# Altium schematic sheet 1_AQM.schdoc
size 309 x 223 mm; Symbol: Sheet-Symbol_A4; Device: Sheet-Symbol_A4; @Project Name: Air Quality Monitor; @Page Count: 1; @Update Date: 2024-08-29; @Create Date: 2024-08-23; @Schematic Name: Schematic1; @Page No: 1; @Page Name: AQM; Company: EasyEDA.com; Reviewed: EasyEDA; Version: V0.1; Page Size: A4; Part Number: JLCPCB-002; Drawn: EasyEDA; @Board Name: Board1; @Create Time: 15:16:23; @Update Time: 16:29:40
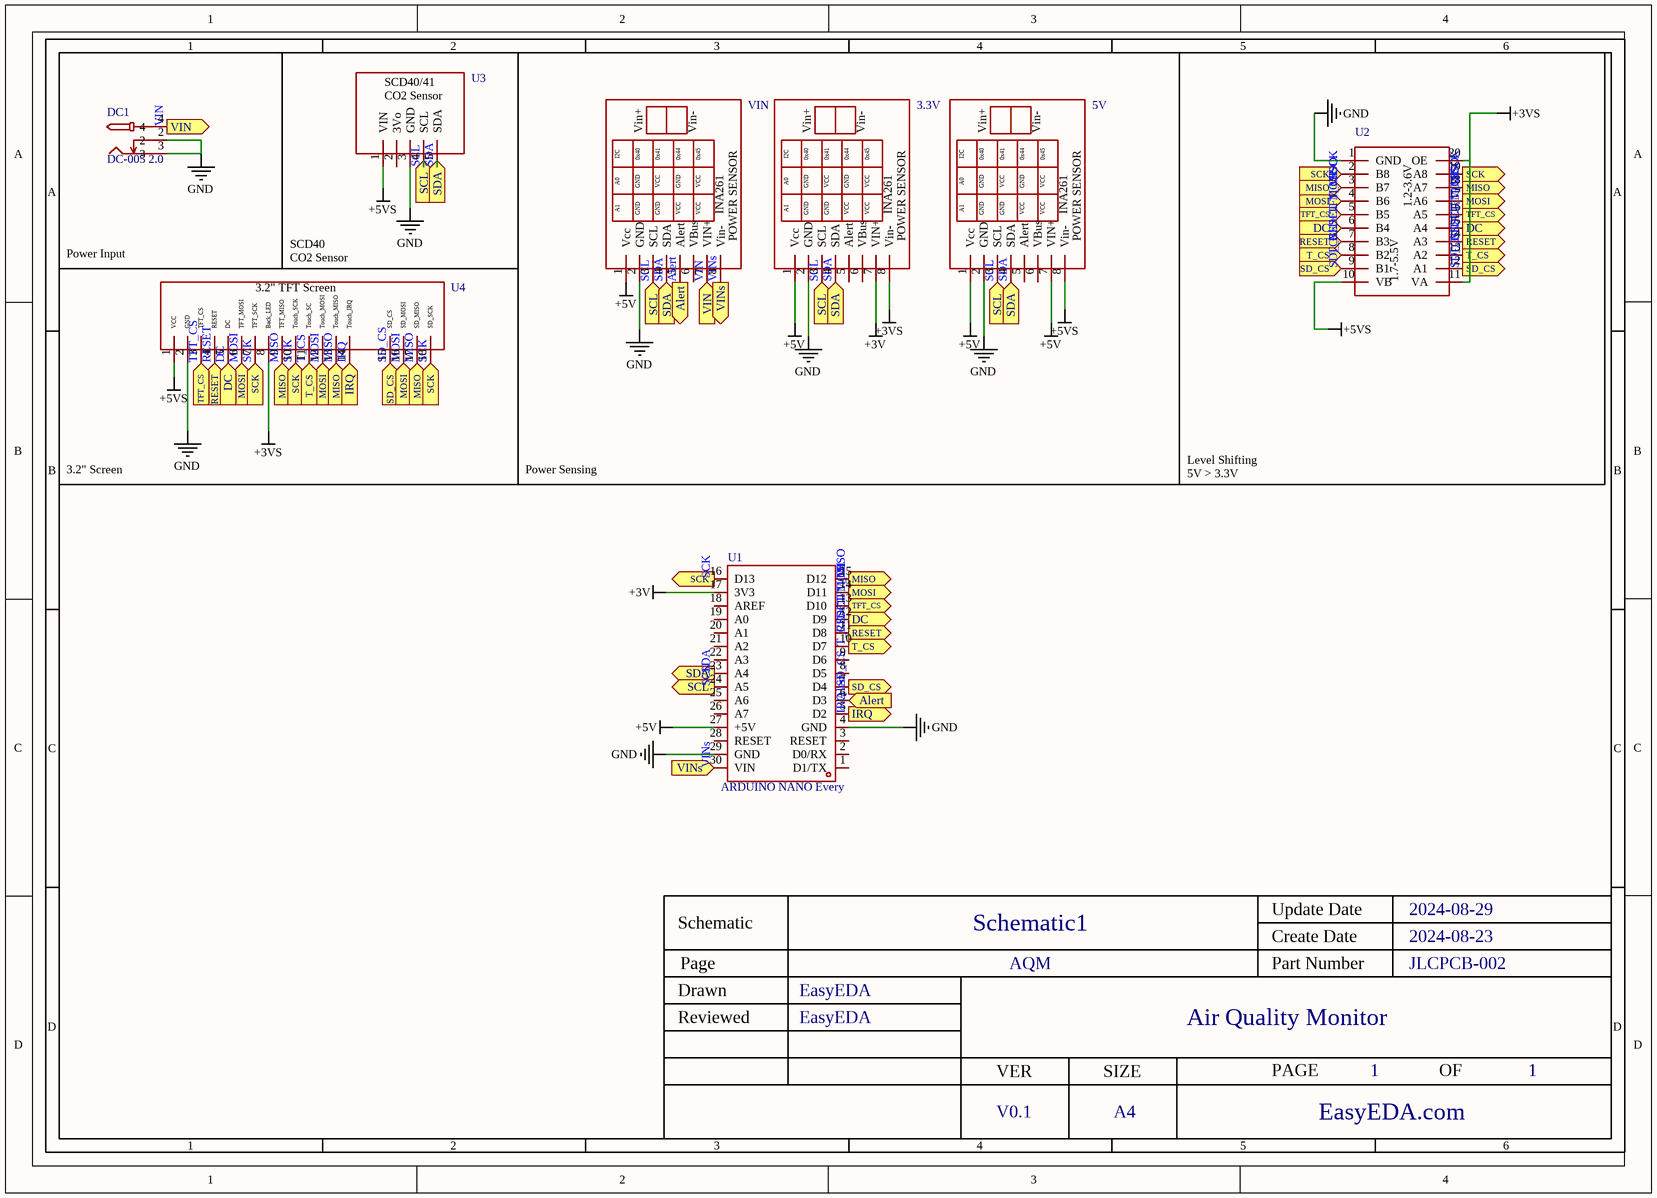
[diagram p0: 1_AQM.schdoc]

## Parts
3.3V  INA260 Breakout  [INA260 Breakout]  (value not drawn)
5V  INA260 Breakout  [INA260 Breakout]  (value not drawn)
DC1  DC-005 2.0  [DC-IN-TH_DC-5520-1]  (value not drawn)
U1  ARDUINO NANO Every  [COMM-TH_ARDUINO_NANO]  (value not drawn)
U2  8 Channel Level Shifter  [8 Channel Level Shifter Footprint]  (value not drawn)
U3  Adafruit SCD40/41 Breakout  [Adafruit SCD40/41]  (value not drawn)
U4  2.8" TFT Screen (SPI, Touch, SD)  [2.8" TFT Display Footprint 1]  (value not drawn)
VIN  INA260 Breakout  [INA260 Breakout]  (value not drawn)

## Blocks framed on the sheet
Power Input: DC1
Power Sensing: 3.3V 5V VIN
3.2" Screen: U4

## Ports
Alert (in), Alert (out), DC (in), DC (out), IRQ (in), IRQ (out), MISO (in), MISO (out), MOSI (in), MOSI (out), RESET (in), RESET (out), SCK (in), SCK (out), SCL (in), SCL (out), SD_CS (in), SD_CS (out), SDA (in), SDA (out), T_CS (in), T_CS (out), TFT_CS (in), TFT_CS (out), VIN (in), VIN (out), VINs (in), VINs (out)

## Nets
+3V: 3.3V.7(VIN+) U1.17(3V3)
+3VS: 3.3V.8(Vin-) U2.11(VA) U2.20(OE) U4.8(Back_LED)
+5V: 3.3V.1(Vcc) 5V.1(Vcc) 5V.7(VIN+) U1.27(+5V) VIN.1(Vcc)
+5VS: 5V.8(Vin-) U2.10(VB) U3.1(VIN) U4.1(VCC)
GND: 3.3V.2(GND) 5V.2(GND) DC1.2 DC1.3 U1.4(GND) U1.29(GND) U2.1(GND) U3.3(GND) U4.2(GND) VIN.2(GND)
Alert: U1.6(D3) VIN.5(Alert) ; port Alert
DC: U1.12(D9) U2.6(B4) U2.15(A4) U4.5(DC) ; port DC
IRQ: U1.5(D2) U4.14(Touch_IRQ) ; port IRQ
MISO: U1.15(D12) U2.3(B7) U2.18(A7) U4.9(TFT_MISO) U4.13(Touch_MISO) U4.17(SD_MISO) ; port MISO
MOSI: U1.14(D11) U2.4(B6) U2.17(A6) U4.6(TFT_MOSI) U4.12(Touch_MOSI) U4.16(SD_MOSI) ; port MOSI
RESET: U1.11(D8) U2.7(B3) U2.14(A3) U4.4(RESET) ; port RESET
SCK: U1.16(D13) U2.2(B8) U2.19(A8) U4.7(TFT_SCK) U4.10(Touch_SCK) U4.18(SD_SCK) ; port SCK
SCL: 3.3V.3(SCL) 5V.3(SCL) U1.24(A5) U3.4(SCL) VIN.3(SCL) ; port SCL
SD_CS: U1.7(D4) U2.9(B1) U2.12(A1) U4.15(SD_CS) ; port SD_CS
SDA: 3.3V.4(SDA) 5V.4(SDA) U1.23(A4) U3.5(SDA) VIN.4(SDA) ; port SDA
T_CS: U1.10(D7) U2.8(B2) U2.13(A2) U4.11(Touch_SC) ; port T_CS
TFT_CS: U1.13(D10) U2.5(B5) U2.16(A5) U4.3(TFT_CS) ; port TFT_CS
VIN: DC1.4 VIN.7(VIN+) ; port VIN
VINs: U1.30(VIN) VIN.8(Vin-) ; port VINs

Not connected (* = marked no-connect by the designer): 3.3V 5(Alert) 6(VBus); 5V 5(Alert) 6(VBus); U1 1(D1/TX) 2(D0/RX) 3(RESET) 8(D5) 9(D6) 18(AREF) 19(A0) 20(A1) 21(A2) 22(A3) 25(A6) 26(A7) 28(RESET); U3 2(3Vo); VIN 6(VBus)

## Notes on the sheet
- (near U4) SCD40
  CO2 Sensor
- Level Shifting
  5V > 3.3V

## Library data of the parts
3.3V 5V VIN = INA260 Breakout: Adafruit INA260 High or Low Side Voltage, Current, Power Sensor; Add into BOM: yes
DC1 = DC-005 2.0: Connector Type:DC Power Receptacle Mounting Style:Right-Angle Inside Contact Diameter:2mm Outside Contact Diameter:6.4mm Current Rating (Max):- Voltage Rating (Max):- Operating Temperature Range:- Operating Temperature Range:-; Manufacturer: BOOMELE(博穆精密); Symbol: DC-005 5.5-2.0MM; Add into BOM: yes; Inside Contact Diameter: 2mm; Outside Contact Diameter: 6.4mm
U1 = ARDUINO_NANO: Add into BOM: yes
U2 = 8 Channel Level Shifter: Level Shifter for 8 Channels from 3.3V to 5V; Symbol: 8 Channel Level Shifter Symbol; Add into BOM: yes
U3 = Adafruit SCD40/41 Breakout: Add into BOM: yes
U4 = 2.8" TFT Screen (SPI, Touch, SD): 2.8" TFT Screen with SPI, Touch and SD Card.; Symbol: 3.2" TFT Screen Symbol; Add into BOM: yes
